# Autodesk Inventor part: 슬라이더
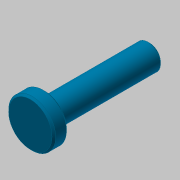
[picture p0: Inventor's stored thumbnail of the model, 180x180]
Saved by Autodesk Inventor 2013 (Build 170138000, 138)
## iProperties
Created: 2019-01
Part Number: 슬라이더
Material: 강철, 연강
Document SubType Name: Modeling
Designer: mduedu
Density: 7.86 g/cm^3
Mass: 101.006 g
Surface Area: 43.3118 cm^2
Volume: 12.8506 cm^3
Author: mduedu
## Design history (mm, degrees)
sketch "스케치1"
  geometry: L1 (0, 0)-(8, 0); L2 (8, 0)-(8, 13); L3 (8, 13)-(0, 13); L4 (0, 13)-(0, 0); L5 (8, 0)-(66, 0); L6 (66, 0)-(66, 7); L7 (66, 7)-(8, 7); L8 (8, 7)-(8, 0)
  constraints: 16 end point, 4 parallel, 2 horizontal, 2 perpendicular
  dimensions: "d0" = 66 distance between parallel lines of L6 L4; "d2" = 8 distance of L2.end L3.end; "d3" = 26 diameter of L3 L1; "d4" = 14 diameter of L7 L5
revolve "회전1" sketch "스케치1" stored, may be unused: angle "d5" = 90 deg
chamfer "모따기1" distance "d6" = 1; stored, may be unused: second distance "d7" = 2, angle "d8" = 45 deg
hole "구멍1" diameter "d14" = 4.134; stored, may be unused: countersink angle "d18" = 60 deg, drill point angle "d20" = 118 deg; dims "d15" = 12, "d16" = 6.3, "d17" = 2, "d19" = 15, "d26" = 10, "d27" = 10
chamfer "모따기4" distance "d24" = 1; stored, may be unused: second distance "d25" = 2, angle "d28" = 30 deg
sketch "스케치2"
  geometry: L1 (66, 2.067)-(66, -2.067) reference; L2 (66, 0)-(64, 0); L3 (64, 0)-(64, 2.067); L4 (66, 3.222)-(66, 0); L5 (66, 3.222)-(64, 2.067); L6 (51, 2.067)-(66, 2.067) reference; 1 further point
  constraints: 8 end point, 1 horizontal, 1 midpoint, 1 parallel, 1 perpendicular, 1 point on line
  dimensions: "d29" = 2 horizontal distance of L4.start L3.end; "d31" = 30 deg angle of L2 L5
revolve "회전2" sketch "스케치2" stored, may be unused: angle "d33" = 90 deg
node "솔리드1"
